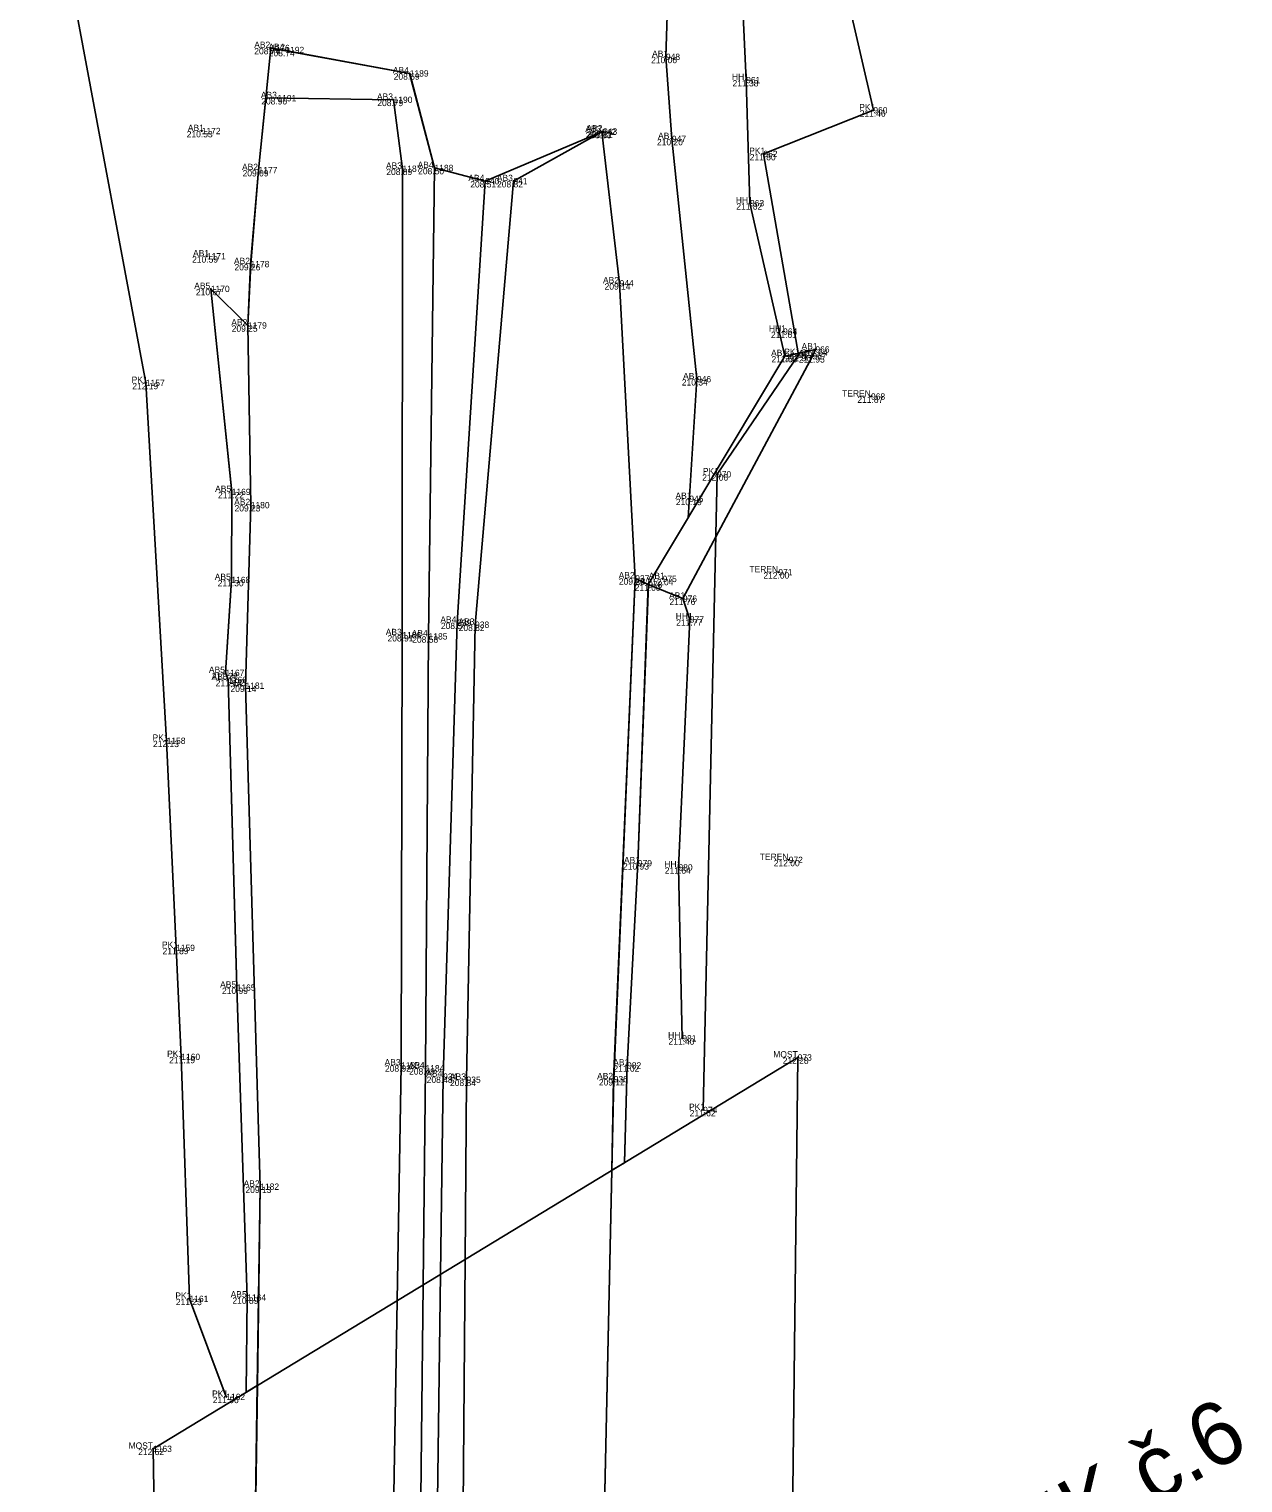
# Model space of a CAD drawing. Extents: x -263091 to -262565, y -1238731 to -1237092.
# Drawn here: x -262751.52 to -262713.19, y -1237292.89 to -1237246.95 of the extents above; entities that cross this region are included whole.
import ezdxf

# ---------------------------------------------------------------- set-up
doc = ezdxf.new("R2010")
doc.units = 0
for name, color, linetype in [('01_Hrana_betónu', 7, 'Continuous'), ('02_Oplotenie', 7, 'Continuous'), ('04_Most', 7, 'Continuous'), ('05_Hrana_terénu', 7, 'Continuous'), ('09_Múrik', 7, 'Continuous'), ('10', 7, 'Continuous'), ('Groma (21)', 7, 'Continuous'), ('Groma (22)', 7, 'Continuous'), ('Groma (23)', 7, 'Continuous'), ('Groma (24)', 7, 'Continuous'), ('U005_Betónový_múrik', 7, 'Continuous'), ('U006_Betónové_panely', 7, 'Continuous')]:
    doc.layers.add(name, color=color, linetype=linetype)

# ---------------------------------------------------------------- blocks, each defined once
blk = doc.blocks.new('POINT_DISPLAY')
blk.add_line((0, 0), (0, 0))

msp = doc.modelspace()

# ---------------------------------------------------------------- linework, layer by layer
at = {"layer": '01_Hrana_betónu'}
for points in [[(-262731.851, -1237224.086), (-262732.01, -1237224.888), (-262733.251, -1237224.584), (-262734.328, -1237223.957), (-262733.383, -1237226.46), (-262732.174, -1237230.423), (-262731.033, -1237236.107), (-262731.406, -1237247.829), (-262731.217, -1237250.422), (-262730.427, -1237258.013), (-262730.707, -1237262.398)], [(-262743.883, -1237247.547), (-262744.041, -1237249.128), (-262744.269, -1237251.407), (-262744.524, -1237254.376), (-262744.607, -1237256.316)], [(-262743.883, -1237247.547), (-262739.496, -1237248.352), (-262738.714, -1237251.34), (-262738.901, -1237266.14), (-262739, -1237279.788), (-262739.074, -1237286.63)], [(-262739.895, -1237287.128), (-262739.767, -1237279.696), (-262739.731, -1237266.101), (-262739.724, -1237251.364), (-262740.007, -1237249.185), (-262744.041, -1237249.128)], [(-262733.43, -1237250.203), (-262737.112, -1237251.756), (-262737.996, -1237265.709), (-262738.44, -1237280.05), (-262738.523, -1237286.295)], [(-262737.748, -1237285.825), (-262737.703, -1237280.149), (-262737.434, -1237265.771), (-262736.222, -1237251.754), (-262733.43, -1237250.203)], [(-262733.43, -1237250.203), (-262732.87, -1237254.983), (-262732.375, -1237264.307)], [(-262727.648, -1237257.282), (-262726.686, -1237257.072), (-262726.783, -1237257.288), (-262730.869, -1237264.948), (-262731.964, -1237264.502), (-262727.648, -1237257.282)], [(-262737.894, -1237304.051), (-262737.748, -1237285.825)], [(-262738.523, -1237286.295), (-262738.767, -1237304.582)], [(-262739.074, -1237286.63), (-262739.271, -1237304.89)], [(-262740.209, -1237305.461), (-262739.895, -1237287.128)]]:
    msp.add_lwpolyline(points, dxfattribs=at)
at = {"layer": '02_Oplotenie'}
for points in [[(-262745.291, -1237290.168), (-262746.451, -1237287.071), (-262746.711, -1237279.427), (-262746.875, -1237275.982), (-262747.173, -1237269.439), (-262747.831, -1237258.131), (-262750.035, -1237246.355), (-262747.946, -1237241.849), (-262746.811, -1237242.447), (-262745.123, -1237240.039), (-262743.124, -1237235.94), (-262742.995, -1237231.474), (-262744.402, -1237227.257), (-262747.587, -1237224.08), (-262751.517, -1237222.073)], [(-262728.187, -1237235.058), (-262724.856, -1237249.517), (-262728.33, -1237250.897), (-262727.224, -1237257.246), (-262729.793, -1237261.019), (-262730.23, -1237281.105)]]:
    msp.add_lwpolyline(points, dxfattribs=at)
at = {"layer": '04_Most'}
msp.add_lwpolyline([(-262747.604, -1237291.81), (-262727.245, -1237279.446), (-262727.45, -1237297.689), (-262747.304, -1237309.783)], close=True, dxfattribs=at)
at = {"layer": '05_Hrana_terénu'}
for points in [[(-262731.351, -1237225.503), (-262729.482, -1237235.388), (-262728.873, -1237248.563), (-262728.752, -1237252.453), (-262727.648, -1237257.282)], [(-262730.869, -1237264.948), (-262730.65, -1237265.604), (-262731.01, -1237273.439), (-262730.89, -1237278.841)]]:
    msp.add_lwpolyline(points, dxfattribs=at)
at = {"layer": '09_Múrik'}
for points in [[(-262744.659, -1237290.021), (-262744.628, -1237287.029), (-262744.961, -1237277.238), (-262745.232, -1237267.514), (-262745.315, -1237267.293), (-262745.13, -1237264.357), (-262745.119, -1237261.575), (-262745.779, -1237255.161), (-262744.607, -1237256.316)], [(-262744.607, -1237256.316), (-262744.517, -1237261.993), (-262744.684, -1237267.698), (-262744.217, -1237283.528), (-262744.309, -1237289.809)], [(-262732.375, -1237264.307), (-262733.056, -1237280.131), (-262733.118, -1237283.012)], [(-262732.712, -1237282.766), (-262732.634, -1237279.698), (-262732.293, -1237273.308), (-262731.964, -1237264.502), (-262732.375, -1237264.307)], [(-262733.118, -1237283.012), (-262733.51, -1237301.38)], [(-262744.309, -1237289.809), (-262744.576, -1237308.121)]]:
    msp.add_lwpolyline(points, dxfattribs=at)
at = {"layer": 'Groma (21)'}
for centre in [(-262743.883, -1237247.547), (-262743.425, -1237247.612), (-262731.406, -1237247.829), (-262739.496, -1237248.352), (-262728.873, -1237248.563), (-262743.674, -1237249.133), (-262740.007, -1237249.185), (-262724.856, -1237249.517), (-262746.066, -1237250.172), (-262733.43, -1237250.203), (-262733.39, -1237250.186), (-262731.217, -1237250.422), (-262728.33, -1237250.897), (-262744.269, -1237251.407), (-262739.724, -1237251.364), (-262738.714, -1237251.34), (-262737.112, -1237251.756), (-262736.222, -1237251.754), (-262728.752, -1237252.453), (-262745.901, -1237254.131), (-262744.524, -1237254.376), (-262745.779, -1237255.161), (-262732.87, -1237254.983), (-262744.607, -1237256.316), (-262727.706, -1237256.509), (-262727.648, -1237257.282), (-262727.224, -1237257.246), (-262726.783, -1237257.288), (-262726.686, -1237257.072), (-262747.831, -1237258.131), (-262730.427, -1237258.013), (-262724.93, -1237258.561), (-262729.793, -1237261.019), (-262745.119, -1237261.575), (-262744.517, -1237261.993), (-262730.668, -1237261.794), (-262745.13, -1237264.357), (-262732.375, -1237264.307), (-262731.511, -1237264.325), (-262727.856, -1237264.114), (-262731.964, -1237264.502), (-262730.869, -1237264.948), (-262737.996, -1237265.709), (-262730.65, -1237265.604), (-262739.731, -1237266.101), (-262738.901, -1237266.14), (-262737.434, -1237265.771), (-262745.315, -1237267.293), (-262745.232, -1237267.514), (-262744.684, -1237267.698), (-262747.173, -1237269.439), (-262732.293, -1237273.308), (-262731.01, -1237273.439), (-262727.529, -1237273.203), (-262746.875, -1237275.982), (-262744.961, -1237277.238), (-262730.89, -1237278.841), (-262746.711, -1237279.427), (-262727.245, -1237279.446), (-262739.767, -1237279.696), (-262739, -1237279.788), (-262732.634, -1237279.698), (-262738.44, -1237280.05), (-262737.703, -1237280.149), (-262733.056, -1237280.131), (-262730.23, -1237281.105), (-262744.217, -1237283.528), (-262746.451, -1237287.071), (-262744.628, -1237287.029), (-262745.291, -1237290.168), (-262747.604, -1237291.81)]:
    msp.add_circle(centre, 0.01, dxfattribs=at)
at = {"layer": 'U005_Betónový_múrik'}
for points in [[(-262744.31, -1237289.81), (-262744.66, -1237290.02), (-262744.63, -1237287.03), (-262744.96, -1237277.24), (-262745.23, -1237267.51), (-262745.32, -1237267.29), (-262745.13, -1237264.36), (-262745.12, -1237261.58), (-262745.78, -1237255.16), (-262744.61, -1237256.32), (-262744.52, -1237261.99), (-262744.68, -1237267.7), (-262744.22, -1237283.53)], [(-262732.29, -1237273.31), (-262732.63, -1237279.7), (-262732.71, -1237282.77), (-262733.12, -1237283.01), (-262733.06, -1237280.13), (-262732.38, -1237264.31), (-262731.96, -1237264.5)]]:
    msp.add_lwpolyline(points, close=True, dxfattribs=at)
for points in [[(-262744.22, -1237283.53), (-262744.31, -1237289.81), (-262744.66, -1237290.02), (-262744.63, -1237287.03), (-262744.96, -1237277.24), (-262745.23, -1237267.51), (-262745.32, -1237267.29), (-262745.13, -1237264.36), (-262745.12, -1237261.58), (-262745.78, -1237255.16), (-262744.61, -1237256.32), (-262744.52, -1237261.99), (-262744.68, -1237267.7), (-262744.22, -1237283.53)], [(-262731.96, -1237264.5), (-262732.29, -1237273.31), (-262732.63, -1237279.7), (-262732.71, -1237282.77), (-262733.12, -1237283.01), (-262733.06, -1237280.13), (-262732.38, -1237264.31), (-262731.96, -1237264.5)]]:
    msp.add_lwpolyline(points, dxfattribs=at)
at = {"layer": 'U006_Betónové_panely'}
msp.add_lwpolyline([(-262744.58, -1237308.12), (-262744.31, -1237289.81), (-262744.22, -1237283.53), (-262744.68, -1237267.7), (-262744.52, -1237261.99), (-262744.61, -1237256.32), (-262744.52, -1237254.38), (-262744.27, -1237251.41), (-262744.04, -1237249.13), (-262743.88, -1237247.55), (-262739.5, -1237248.35), (-262738.71, -1237251.34), (-262737.11, -1237251.76), (-262733.43, -1237250.2), (-262732.87, -1237254.98), (-262732.38, -1237264.31), (-262733.06, -1237280.13), (-262733.12, -1237283.01), (-262733.51, -1237301.38)], dxfattribs=at)
msp.add_lwpolyline([(-262744.58, -1237308.12), (-262744.31, -1237289.81), (-262744.22, -1237283.53), (-262744.68, -1237267.7), (-262744.52, -1237261.99), (-262744.61, -1237256.32), (-262744.52, -1237254.38), (-262744.27, -1237251.41), (-262744.04, -1237249.13), (-262743.88, -1237247.55), (-262739.5, -1237248.35), (-262738.71, -1237251.34), (-262737.11, -1237251.76), (-262733.43, -1237250.2), (-262732.87, -1237254.98), (-262732.38, -1237264.31), (-262733.06, -1237280.13), (-262733.12, -1237283.01), (-262733.51, -1237301.38)], dxfattribs=at)

# ---------------------------------------------------------------- block references
at = {"layer": '01_Hrana_betónu'}
msp.add_blockref('POINT_DISPLAY', (-262727.648, -1237257.282), dxfattribs=at)

# ---------------------------------------------------------------- texts
at = {"layer": '10'}
msp.add_text('ÚSEK č.6', height=2, rotation=28.7018, dxfattribs=at).set_placement((-262723.09, -1237297.438))
at = {"layer": 'Groma (22)'}
for s, p in [('1176', (-262743.883, -1237247.647)), ('1192', (-262743.425, -1237247.712)), ('948', (-262731.406, -1237247.929)), ('1189', (-262739.496, -1237248.452)), ('961', (-262728.873, -1237248.663)), ('1191', (-262743.674, -1237249.233)), ('1190', (-262740.007, -1237249.285)), ('960', (-262724.856, -1237249.617)), ('1172', (-262746.066, -1237250.272)), ('942', (-262733.43, -1237250.303)), ('943', (-262733.39, -1237250.286)), ('947', (-262731.217, -1237250.522)), ('962', (-262728.33, -1237250.997)), ('1177', (-262744.269, -1237251.507)), ('1187', (-262739.724, -1237251.464)), ('1188', (-262738.714, -1237251.44)), ('940', (-262737.112, -1237251.856)), ('941', (-262736.222, -1237251.854)), ('963', (-262728.752, -1237252.553)), ('1171', (-262745.901, -1237254.231)), ('1178', (-262744.524, -1237254.476)), ('1170', (-262745.779, -1237255.261)), ('944', (-262732.87, -1237255.083)), ('1179', (-262744.607, -1237256.416)), ('964', (-262727.706, -1237256.609)), ('966', (-262726.686, -1237257.172)), ('965', (-262727.648, -1237257.382)), ('969', (-262727.224, -1237257.346)), ('967', (-262726.783, -1237257.388)), ('946', (-262730.427, -1237258.113)), ('1157', (-262747.831, -1237258.231)), ('968', (-262724.93, -1237258.661)), ('970', (-262729.793, -1237261.119)), ('1169', (-262745.119, -1237261.675)), ('1180', (-262744.517, -1237262.093)), ('945', (-262730.668, -1237261.894)), ('1168', (-262745.13, -1237264.457)), ('937', (-262732.375, -1237264.407)), ('975', (-262731.511, -1237264.425)), ('971', (-262727.856, -1237264.214)), ('978', (-262731.964, -1237264.602)), ('976', (-262730.869, -1237265.048)), ('939', (-262737.996, -1237265.809)), ('938', (-262737.434, -1237265.871)), ('977', (-262730.65, -1237265.704)), ('1186', (-262739.731, -1237266.201)), ('1185', (-262738.901, -1237266.24)), ('1167', (-262745.315, -1237267.393)), ('1166', (-262745.232, -1237267.614)), ('1181', (-262744.684, -1237267.798)), ('1158', (-262747.173, -1237269.539)), ('979', (-262732.293, -1237273.408)), ('980', (-262731.01, -1237273.539)), ('972', (-262727.529, -1237273.303)), ('1159', (-262746.875, -1237276.082)), ('1165', (-262744.961, -1237277.338)), ('981', (-262730.89, -1237278.941)), ('1160', (-262746.711, -1237279.527)), ('973', (-262727.245, -1237279.546)), ('1183', (-262739.767, -1237279.796)), ('1184', (-262739, -1237279.888)), ('934', (-262738.44, -1237280.15)), ('982', (-262732.634, -1237279.798)), ('935', (-262737.703, -1237280.249)), ('936', (-262733.056, -1237280.231)), ('974', (-262730.23, -1237281.205)), ('1182', (-262744.217, -1237283.628)), ('1161', (-262746.451, -1237287.171)), ('1164', (-262744.628, -1237287.129)), ('1162', (-262745.291, -1237290.268)), ('1163', (-262747.604, -1237291.91))]:
    msp.add_text(s, height=0.2, dxfattribs=at).set_placement(p)
at = {"layer": 'Groma (23)'}
for s, p in [('208.74', (-262744.405, -1237247.747)), ('208.74', (-262743.947, -1237247.812)), ('210.06', (-262731.874, -1237248.029)), ('208.69', (-262740.003, -1237248.552)), ('211.38', (-262729.304, -1237248.763)), ('208.90', (-262744.185, -1237249.333)), ('208.79', (-262740.52, -1237249.385)), ('211.46', (-262725.287, -1237249.717)), ('210.53', (-262746.539, -1237250.372)), ('208.83', (-262733.947, -1237250.403)), ('208.82', (-262733.907, -1237250.386)), ('210.20', (-262731.689, -1237250.622)), ('211.80', (-262728.76, -1237251.097)), ('209.09', (-262744.775, -1237251.607)), ('208.89', (-262740.236, -1237251.564)), ('208.50', (-262739.23, -1237251.54)), ('208.51', (-262737.585, -1237251.956)), ('208.82', (-262736.739, -1237251.954)), ('211.82', (-262729.183, -1237252.653)), ('210.59', (-262746.369, -1237254.331)), ('209.26', (-262745.031, -1237254.576)), ('210.67', (-262746.248, -1237255.361)), ('209.14', (-262733.343, -1237255.183)), ('209.25', (-262745.119, -1237256.516)), ('211.61', (-262728.089, -1237256.709)), ('211.60', (-262728.073, -1237257.482)), ('211.96', (-262727.645, -1237257.446)), ('211.95', (-262727.209, -1237257.488)), ('211.64', (-262727.117, -1237257.272)), ('212.19', (-262748.257, -1237258.331)), ('210.34', (-262730.905, -1237258.213)), ('211.87', (-262725.361, -1237258.761)), ('212.06', (-262730.261, -1237261.219)), ('211.22', (-262745.55, -1237261.775)), ('209.23', (-262745.029, -1237262.193)), ('210.19', (-262731.093, -1237261.994)), ('209.24', (-262732.892, -1237264.507)), ('212.04', (-262731.989, -1237264.525)), ('212.00', (-262728.328, -1237264.314)), ('211.30', (-262745.56, -1237264.557)), ('211.00', (-262732.393, -1237264.702)), ('211.76', (-262731.296, -1237265.148)), ('208.57', (-262738.513, -1237265.909)), ('211.77', (-262731.082, -1237265.804)), ('208.91', (-262740.199, -1237266.301)), ('208.58', (-262739.418, -1237266.34)), ('208.82', (-262737.951, -1237265.971)), ('211.38', (-262745.746, -1237267.493)), ('211.14', (-262745.624, -1237267.714)), ('209.14', (-262745.157, -1237267.898)), ('212.13', (-262747.604, -1237269.639)), ('210.93', (-262732.761, -1237273.508)), ('211.64', (-262731.441, -1237273.639)), ('212.00', (-262728.001, -1237273.403)), ('211.89', (-262747.301, -1237276.182)), ('210.99', (-262745.425, -1237277.438)), ('211.40', (-262731.325, -1237279.041)), ('211.19', (-262747.094, -1237279.627)), ('212.28', (-262727.719, -1237279.646)), ('208.92', (-262740.279, -1237279.896)), ('208.49', (-262739.517, -1237279.988)), ('211.02', (-262733.064, -1237279.898)), ('208.48', (-262738.961, -1237280.25)), ('208.84', (-262738.224, -1237280.349)), ('209.12', (-262733.524, -1237280.331)), ('211.62', (-262730.656, -1237281.305)), ('209.13', (-262744.685, -1237283.728)), ('211.23', (-262746.882, -1237287.271)), ('210.89', (-262745.096, -1237287.229)), ('211.56', (-262745.717, -1237290.368)), ('212.62', (-262748.073, -1237292.01))]:
    msp.add_text(s, height=0.2, dxfattribs=at).set_placement(p)
at = {"layer": 'Groma (24)'}
for s, p in [('AB2', (-262744.407, -1237247.547)), ('AB4', (-262743.959, -1237247.612)), ('AB1', (-262731.844, -1237247.829)), ('AB4', (-262740.03, -1237248.352)), ('HH1', (-262729.32, -1237248.563)), ('AB3', (-262744.198, -1237249.133)), ('AB3', (-262740.531, -1237249.185)), ('PK1', (-262725.303, -1237249.517)), ('AB1', (-262746.504, -1237250.172)), ('AB3', (-262733.954, -1237250.203)), ('AB2', (-262733.914, -1237250.186)), ('AB1', (-262731.655, -1237250.422)), ('PK1', (-262728.777, -1237250.897)), ('AB2', (-262744.793, -1237251.407)), ('AB3', (-262740.248, -1237251.364)), ('AB4', (-262739.248, -1237251.34)), ('AB4', (-262737.646, -1237251.756)), ('AB3', (-262736.746, -1237251.754)), ('HH1', (-262729.199, -1237252.453)), ('AB1', (-262746.339, -1237254.131)), ('AB2', (-262745.048, -1237254.376)), ('AB5', (-262746.303, -1237255.161)), ('AB2', (-262733.394, -1237254.983)), ('AB2', (-262745.131, -1237256.316)), ('HH1', (-262728.153, -1237256.509)), ('AB1', (-262727.124, -1237257.072)), ('AB1', (-262728.086, -1237257.282)), ('PK1', (-262727.671, -1237257.246)), ('AB1', (-262727.221, -1237257.288)), ('AB1', (-262730.865, -1237258.013)), ('PK1', (-262748.278, -1237258.131)), ('TEREN', (-262725.845, -1237258.561)), ('PK1', (-262730.24, -1237261.019)), ('AB5', (-262745.643, -1237261.575)), ('AB1', (-262731.106, -1237261.794)), ('AB2', (-262745.041, -1237261.993)), ('AB5', (-262745.654, -1237264.357)), ('AB2', (-262732.899, -1237264.307)), ('AB1', (-262732.402, -1237264.502)), ('AB1', (-262731.949, -1237264.325)), ('TEREN', (-262728.771, -1237264.114)), ('AB1', (-262731.307, -1237264.948)), ('AB4', (-262738.53, -1237265.709)), ('AB3', (-262737.958, -1237265.771)), ('HH1', (-262731.097, -1237265.604)), ('AB3', (-262740.255, -1237266.101)), ('AB4', (-262739.435, -1237266.14)), ('AB5', (-262745.839, -1237267.293)), ('AB5', (-262745.756, -1237267.514)), ('AB2', (-262745.208, -1237267.698)), ('PK1', (-262747.62, -1237269.439)), ('TEREN', (-262728.444, -1237273.203)), ('AB1', (-262732.731, -1237273.308)), ('HH1', (-262731.457, -1237273.439)), ('PK1', (-262747.322, -1237275.982)), ('AB5', (-262745.485, -1237277.238)), ('HH1', (-262731.337, -1237278.841)), ('PK1', (-262747.158, -1237279.427)), ('AB3', (-262740.291, -1237279.696)), ('AB1', (-262733.072, -1237279.698)), ('MOST', (-262728.017, -1237279.446)), ('AB4', (-262739.534, -1237279.788)), ('AB4', (-262738.974, -1237280.05)), ('AB3', (-262738.227, -1237280.149)), ('AB2', (-262733.58, -1237280.131)), ('PK1', (-262730.677, -1237281.105)), ('AB2', (-262744.741, -1237283.528)), ('AB5', (-262745.152, -1237287.029)), ('PK1', (-262746.898, -1237287.071)), ('PK1', (-262745.738, -1237290.168)), ('MOST', (-262748.376, -1237291.81))]:
    msp.add_text(s, height=0.2, dxfattribs=at).set_placement(p)

doc.saveas('drawing.dxf')
